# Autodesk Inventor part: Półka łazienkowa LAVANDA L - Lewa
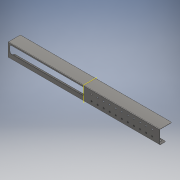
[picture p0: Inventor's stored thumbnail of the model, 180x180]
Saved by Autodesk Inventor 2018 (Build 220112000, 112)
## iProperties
Created: 2020-02
Part Number: Półka łazienkowa LAVANDA L - Lewa
Material: Ogólny
Document SubType Name: Modeling
Designer: Marcel
Density: 1 g/cm^3
Appearance: Domyślna
Author: Marcel
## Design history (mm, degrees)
derived "Półka łazienkowa LAVANDA L - Lewa.iam"
node "Bryła1"
node "Uchwyt na ręcznik 1.ipt:1"
node "Płaszczyzna konstrukcyjna1"
node "Kapselek.ipt:1"
node "Kapselek.ipt:2"
node "Kapselek.ipt:3"
